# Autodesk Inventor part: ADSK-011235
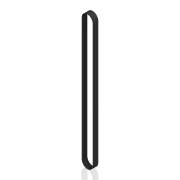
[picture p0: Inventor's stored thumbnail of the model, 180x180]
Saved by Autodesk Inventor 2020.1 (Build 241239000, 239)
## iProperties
Created: 1999-12
Part Number: ADSK-011235
Document SubType Name: Modeling
Designer: sspink
Material: Générique
Density: 1 g/cm^3
Appearance: Rubber-Black
Mass: 126.185 g
Surface Area: 1655.86 cm^2
Volume: 126.185 cm^3
Control State: 0
Checked Out: False
Master: False
Shininess: 0.0
Length Units: 11272
Angle Units: 11279
Time Units: 11290
Mass Units: 11286
Length Display Precision: 3
Angle Display Precision: 2
Compacted: True
Dimensions: 3,2x39,2x1,5 in
Mass: 0,278 lb
DocNumber: ADSK-011235.ipt
Folder: 01 - Themengebiete\Simplification\01 - Packaging machine\
VDS_Category: 3D Komponenten
Density: 0.0
Volumn: 0.0
Area: 0.0
PropertySet Name: Model Information
Author: sspink
Revision Number: -
Title: belt
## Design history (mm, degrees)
node "Extrusion1" dims "d5" = 38.1635, "d6" = 0
workplane "Arbeitsebene1"
node "Solide1"
node "Corps solides"
node "Corps surfaciques"
sketch "Sketch1"
  geometry: L1 (-16.928, 0)-(-16.928, -914.4); L2 (-15.341, 0)-(-15.341, -914.4); L3 (63.92, 0)-(63.92, -914.4); L4 (65.507, 0)-(65.507, -914.4); A1 r 39.63 centre (24.29, 0) between (63.92, 0) and (-15.341, 0); A2 r 41.218 centre (24.29, 0) between (65.507, 0) and (-16.928, 0); A3 r 39.63 centre (24.29, -914.4) between (-15.341, -914.4) and (63.92, -914.4); A4 r 41.218 centre (24.29, -914.4) between (-16.928, -914.4) and (65.507, -914.4)
  constraints: 8 end point, 8 point on circle, 8 tangent, 4 centre point, 2 coincident, 1 vertical alignment, 1 other
  dimensions: "d0" = 79.2607 diameter of A1; "d1" = 82.4357 diameter of A2; "d2" = 79.2607 diameter of A3 (= d0); "d3" = 82.4357 diameter of A4 (= d1); "d4" = 914.4 distance of A3.centre A1.centre
